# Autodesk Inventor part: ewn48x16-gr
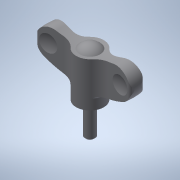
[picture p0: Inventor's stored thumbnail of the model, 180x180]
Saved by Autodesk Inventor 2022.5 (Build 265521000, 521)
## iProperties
Created: 2016-12
Part Number: ewn48x16-gr
Material: 一般
Document SubType Name: Modeling
Designer: imaocorp
Density: 1 g/cm^3
Appearance: 既定
Author: imaocorp
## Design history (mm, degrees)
node "ewn48x16-gr.x_t1"
node "ewn48x16-gr"
node "Base1"
